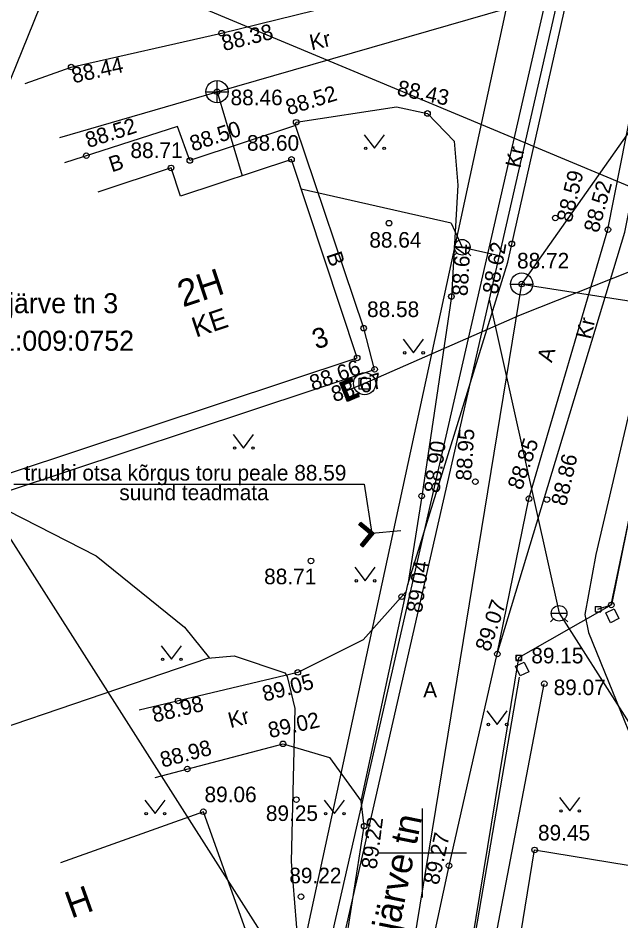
# Model space of a CAD drawing. Extents: x 648748 to 649126, y 6457789 to 6458252.
# Drawn here: x 648931.84 to 648958.94, y 6457996.94 to 6458037.5 of the extents above; entities that cross this region are included whole.
import ezdxf

# ---------------------------------------------------------------- set-up
doc = ezdxf.new("R2010")
doc.units = 0
for name, color, linetype in [('AED', 7, 'Continuous'), ('DKAEV', 7, 'Continuous'), ('HALJASTUS', 7, 'Continuous'), ('HOONE', 7, 'Continuous'), ('HOONEDET', 7, 'Continuous'), ('KKAEV', 7, 'Continuous'), ('KORGUS-EH2000', 7, 'Continuous'), ('KTRASS', 7, 'Continuous'), ('MPOHULIIN', 7, 'Continuous'), ('PIIR', 7, 'Continuous'), ('SIOHULIIN', 7, 'Continuous'), ('SITRASS', 7, 'Continuous'), ('SKTRASS', 7, 'Continuous'), ('TEE', 7, 'Continuous'), ('TRUUP', 7, 'Continuous'), ('VKAEV', 7, 'Continuous'), ('VORK', 7, 'Continuous'), ('VTRASS', 7, 'Continuous')]:
    doc.layers.add(name, color=color, linetype=linetype)

msp = doc.modelspace()

# ---------------------------------------------------------------- linework, layer by layer
at = {"layer": 'AED'}
for p, q in [((648957.78, 6458011.07), (648957.78, 6458010.82)), ((648957.78, 6458011.07), (648958.03, 6458011.07)), ((648957.78, 6458010.82), (648958.03, 6458010.82)), ((648958.03, 6458011.07), (648958.03, 6458010.82)), ((648954.219, 6458008.884), (648954.219, 6458008.634)), ((648954.219, 6458008.884), (648954.469, 6458008.884)), ((648954.469, 6458008.884), (648954.469, 6458008.634)), ((648954.219, 6458008.634), (648954.469, 6458008.634))]:
    msp.add_line(p, q, dxfattribs=at)
for points in [[(648957.905, 6458010.945), (648958.505, 6458011.137), (648959.247, 6458014.712), (648961.658, 6458026.499), (648962.069, 6458028.393), (648963.906, 6458037.666), (648968.07, 6458039.149)], [(648958.257, 6458010.775), (648958.64, 6458010.955), (648958.846, 6458010.521), (648958.463, 6458010.34), (648958.257, 6458010.775)], [(648954.203, 6458008.383), (648954.586, 6458008.564), (648954.792, 6458008.129), (648954.409, 6458007.949), (648954.203, 6458008.383)], [(648950.831, 6457987.974), (648952.234, 6457995.418), (648954.381, 6458007.899)]]:
    msp.add_lwpolyline(points, dxfattribs=at)
at = {"layer": 'DKAEV'}
for p, q in [((648947.167, 6458020.826), (648947.167, 6458021.326)), ((648947.167, 6458021.326), (648947.667, 6458021.326)), ((648947.667, 6458021.326), (648947.667, 6458020.826)), ((648947.667, 6458020.826), (648947.167, 6458020.826))]:
    msp.add_line(p, q, dxfattribs=at)
msp.add_circle((648947.417, 6458021.076), 0.5, dxfattribs=at)
at = {"layer": 'HALJASTUS'}
for p, q in [((648947.404, 6458032.255), (648947.868, 6458031.649)), ((648947.868, 6458031.649), (648948.313, 6458032.255)), ((648949.158, 6458023.067), (648949.621, 6458022.461)), ((648949.621, 6458022.461), (648950.067, 6458023.067)), ((648941.513, 6458018.789), (648941.976, 6458018.182)), ((648941.976, 6458018.182), (648942.422, 6458018.789)), ((648946.983, 6458012.827), (648947.447, 6458012.22)), ((648947.447, 6458012.22), (648947.892, 6458012.827)), ((648938.279, 6458009.303), (648938.742, 6458008.696)), ((648938.742, 6458008.696), (648939.188, 6458009.303)), ((648952.916, 6458006.373), (648953.38, 6458005.766)), ((648953.38, 6458005.766), (648953.825, 6458006.373)), ((648937.539, 6458002.37), (648938.002, 6458001.764)), ((648938.002, 6458001.764), (648938.448, 6458002.37)), ((648945.605, 6458002.37), (648946.068, 6458001.764)), ((648946.068, 6458001.764), (648946.514, 6458002.37)), ((648956.181, 6458002.49), (648956.645, 6458001.883)), ((648956.645, 6458001.883), (648957.09, 6458002.49))]:
    msp.add_line(p, q, dxfattribs=at)
msp.add_lwpolyline([(648952.124, 6457988.956), (648953.251, 6457995.928), (648955.494, 6458007.598)], dxfattribs=at)
for centre in [(648947.467, 6458031.649), (648948.296, 6458031.649), (648949.22, 6458022.461), (648950.049, 6458022.461), (648941.575, 6458018.182), (648942.404, 6458018.182), (648947.046, 6458012.22), (648947.875, 6458012.22), (648938.341, 6458008.696), (648939.17, 6458008.696), (648952.979, 6458005.766), (648953.808, 6458005.766), (648937.601, 6458001.764), (648938.43, 6458001.764), (648945.667, 6458001.764), (648946.496, 6458001.764), (648956.244, 6458001.883), (648957.073, 6458001.883)]:
    msp.add_circle(centre, 0.055, dxfattribs=at)
at = {"layer": 'HOONE'}
for points in [[(648928.367, 6458016.043), (648947.082, 6458022.232), (648944.133, 6458031.148), (648939.141, 6458029.497), (648938.721, 6458030.766), (648935.436, 6458029.68)], [(648928.544, 6457989.915), (648930.412, 6457990.585), (648929.933, 6457991.921), (648942.161, 6457996.306), (648940.174, 6458001.849), (648933.757, 6457999.547)], [(648955.058, 6458000.133), (648960.085, 6457999.314), (648958.123, 6457987.27), (648953.096, 6457988.089), (648955.058, 6458000.133)]]:
    msp.add_lwpolyline(points, dxfattribs=at)
at = {"layer": 'HOONEDET'}
msp.add_lwpolyline([(648928.604, 6458015.329), (648947.87, 6458021.718), (648947.377, 6458023.566), (648944.308, 6458032.668), (648939.566, 6458031.1), (648939.016, 6458032.625), (648933.927, 6458031.001)], dxfattribs=at)
at = {"layer": 'KKAEV'}
for p, q in [((648940.789, 6458033.688), (648940.789, 6458034.688)), ((648940.289, 6458034.188), (648941.289, 6458034.188))]:
    msp.add_line(p, q, dxfattribs=at)
msp.add_circle((648940.789, 6458034.188), 0.5, dxfattribs=at)
at = {"layer": 'KORGUS-EH2000'}
for centre in [(648940.99, 6458036.816), (648934.231, 6458035.294), (648940.789, 6458034.188), (648950.246, 6458033.212), (648944.345, 6458032.817), (648934.911, 6458031.315), (648939.566, 6458031.1), (648944.133, 6458031.148), (648938.721, 6458030.766), (648955.988, 6458028.516), (648948.514, 6458028.286), (648958.354, 6458027.992), (648954.032, 6458027.355), (648954.479, 6458025.55), (648951.32, 6458024.991), (648947.377, 6458023.566), (648947.082, 6458022.232), (648947.87, 6458021.718), (648952.398, 6458016.673), (648949.986, 6458016.028), (648954.806, 6458015.908), (648955.61, 6458015.868), (648945.007, 6458013.112), (648949.087, 6458011.505), (648958.505, 6458011.137), (648953.382, 6458008.934), (648954.344, 6458008.759), (648944.419, 6458008.105), (648955.494, 6458007.598), (648939.039, 6458006.826), (648943.752, 6458004.898), (648939.455, 6458003.768), (648944.351, 6458002.393), (648940.174, 6458001.849), (648947.397, 6458001.199), (648955.058, 6458000.133), (648951.214, 6457999.425), (648944.563, 6457998.032)]:
    msp.add_circle(centre, 0.125, dxfattribs=at)
at = {"layer": 'KTRASS'}
for p, q in [((648940.789, 6458034.188), (648955.59, 6458038.453)), ((648955.59, 6458038.453), (648945.475, 6457994.285)), ((648933.724, 6458032.135), (648940.789, 6458034.188)), ((648940.789, 6458034.188), (648941.911, 6458030.413))]:
    msp.add_line(p, q, dxfattribs=at)
at = {"layer": 'MPOHULIIN'}
for points in [[(648933.863, 6458040.57), (648928.888, 6458028.309)], [(648951.387, 6457937.05), (648959.585, 6457983.976), (648966.776, 6458026.817), (648933.863, 6458040.57)]]:
    msp.add_lwpolyline(points, dxfattribs=at)
at = {"layer": 'PIIR'}
for p, q in [((648941.03, 6457978.89), (648955.2, 6458044.42)), ((648963.88, 6458037.67), (648958.51, 6458011.14)), ((648958.51, 6458011.14), (648954.34, 6458008.76)), ((648954.34, 6458008.76), (648949.37, 6457978.67))]:
    msp.add_line(p, q, dxfattribs=at)
at = {"layer": 'SIOHULIIN'}
msp.add_line((648950.018, 6457985.085), (648929.935, 6458016.562), dxfattribs=at)
at = {"layer": 'SITRASS'}
for points in [[(648966.11, 6458089.841), (648964.318, 6458080.667), (648962.235, 6458070.833), (648961.742, 6458067.306), (648960.68, 6458062.734), (648960.081, 6458059.549), (648958.829, 6458053.903), (648959.436, 6458052.488), (648962.102, 6458051.731), (648964.818, 6458051.004), (648965.35, 6458050.106), (648964.898, 6458046.706), (648961.929, 6458032.449), (648960.742, 6458025.938), (648957.809, 6458013.402), (648957.321, 6458010.707), (648957.473, 6458009.892), (648960.884, 6458001.538), (648961.927, 6457999.033), (648963.394, 6457991.382), (648965.2, 6457986.983), (648965.946, 6457985.459)], [(648929.395, 6458016.383), (648935.351, 6458013.347), (648939.325, 6458010.138), (648940.451, 6458008.746)], [(648924.967, 6458003.499), (648940.379, 6458008.739), (648941.56, 6458008.853), (648943.833, 6458008.084), (648943.941, 6458007.928), (648944.279, 6458006.478), (648944.124, 6457999.614), (648944.415, 6457995.906), (648943.985, 6457992.031), (648941.907, 6457992.28), (648941.694, 6457991.996)]]:
    msp.add_lwpolyline(points, dxfattribs=at)
at = {"layer": 'SKTRASS'}
for p, q in [((648946.306, 6458021.116), (648946.84, 6458021.33)), ((648946.621, 6458021.08), (648946.703, 6458021.275)), ((648946.653, 6458021.093), (648946.736, 6458021.288)), ((648946.686, 6458021.107), (648946.768, 6458021.302)), ((648946.718, 6458021.12), (648946.801, 6458021.315)), ((648946.751, 6458021.133), (648946.834, 6458021.328)), ((648946.784, 6458021.146), (648946.85, 6458021.303)), ((648946.817, 6458021.159), (648946.864, 6458021.27)), ((648946.896, 6458021.191), (648946.84, 6458021.33)), ((648946.642, 6458020.281), (648946.306, 6458021.116)), ((648946.308, 6458021.111), (648946.31, 6458021.117)), ((648946.321, 6458021.078), (648946.343, 6458021.13)), ((648946.334, 6458021.046), (648946.376, 6458021.144)), ((648946.348, 6458021.013), (648946.408, 6458021.157)), ((648946.361, 6458020.98), (648946.441, 6458021.17)), ((648946.374, 6458020.947), (648946.474, 6458021.183)), ((648946.387, 6458020.914), (648946.507, 6458021.196)), ((648946.401, 6458020.881), (648946.539, 6458021.209)), ((648946.404, 6458021.074), (648946.868, 6458021.261)), ((648946.684, 6458020.378), (648946.404, 6458021.074)), ((648946.414, 6458020.848), (648946.572, 6458021.223)), ((648946.427, 6458020.815), (648946.51, 6458021.012)), ((648946.44, 6458020.783), (648946.523, 6458020.979)), ((648946.454, 6458020.75), (648946.536, 6458020.946)), ((648946.467, 6458020.717), (648946.55, 6458020.913)), ((648946.48, 6458020.684), (648946.563, 6458020.88)), ((648946.501, 6458021.032), (648946.896, 6458021.191)), ((648946.725, 6458020.476), (648946.501, 6458021.032)), ((648946.522, 6458021.041), (648946.605, 6458021.236)), ((648946.555, 6458021.054), (648946.637, 6458021.249)), ((648946.588, 6458021.067), (648946.67, 6458021.262)), ((648946.849, 6458021.172), (648946.877, 6458021.238)), ((648946.882, 6458021.186), (648946.89, 6458021.205)), ((648946.493, 6458020.651), (648946.576, 6458020.847)), ((648946.506, 6458020.618), (648946.589, 6458020.814)), ((648946.52, 6458020.585), (648946.602, 6458020.781)), ((648946.533, 6458020.552), (648946.616, 6458020.749)), ((648946.546, 6458020.52), (648946.629, 6458020.716)), ((648946.559, 6458020.487), (648946.642, 6458020.683)), ((648946.573, 6458020.454), (648946.655, 6458020.65)), ((648946.586, 6458020.421), (648946.669, 6458020.617)), ((648946.599, 6458020.388), (648946.682, 6458020.584)), ((648946.612, 6458020.355), (648946.695, 6458020.551)), ((648946.626, 6458020.322), (648946.708, 6458020.518)), ((648946.639, 6458020.289), (648946.722, 6458020.486)), ((648947.176, 6458020.495), (648946.642, 6458020.281)), ((648946.666, 6458020.29), (648946.749, 6458020.485)), ((648947.148, 6458020.565), (648946.684, 6458020.378)), ((648946.699, 6458020.303), (648946.782, 6458020.498)), ((648947.12, 6458020.635), (648946.725, 6458020.476)), ((648946.732, 6458020.317), (648946.814, 6458020.511)), ((648946.764, 6458020.33), (648946.847, 6458020.525)), ((648946.797, 6458020.343), (648946.879, 6458020.538)), ((648946.83, 6458020.356), (648946.912, 6458020.551)), ((648946.863, 6458020.369), (648946.945, 6458020.564)), ((648946.895, 6458020.382), (648946.978, 6458020.577)), ((648946.928, 6458020.396), (648947.01, 6458020.59)), ((648946.961, 6458020.409), (648947.043, 6458020.604)), ((648946.993, 6458020.422), (648947.076, 6458020.617)), ((648947.026, 6458020.435), (648947.109, 6458020.63)), ((648947.059, 6458020.448), (648947.129, 6458020.613)), ((648947.092, 6458020.462), (648947.142, 6458020.58)), ((648947.176, 6458020.495), (648947.12, 6458020.635)), ((648947.124, 6458020.475), (648947.155, 6458020.547)), ((648947.157, 6458020.488), (648947.168, 6458020.514))]:
    msp.add_line(p, q, dxfattribs=at)
for points in [[(648960.26, 6458026.478), (648954.414, 6458024.157), (648947.417, 6458021.076)], [(648947.417, 6458021.076), (648946.544, 6458020.726)]]:
    msp.add_lwpolyline(points, dxfattribs=at)
at = {"layer": 'TEE'}
for points in [[(648944.322, 6457942.691), (648944.43, 6457950.272), (648943.62, 6457959.958), (648943.695, 6457961.993), (648942.732, 6457979.09), (648943.931, 6457987.913), (648944.971, 6457991.084), (648946.572, 6457995.932), (648947.397, 6458001.199), (648947.266, 6458002.317), (648949.36, 6458012.048), (648953.85, 6458026.527), (648957.912, 6458044.595), (648958.876, 6458046.069), (648959.537, 6458047.72), (648961.311, 6458058.347), (648962.735, 6458068.115), (648964.651, 6458078.174), (648966.451, 6458083.821)], [(648949.689, 6457988.093), (648949.022, 6457989.19), (648951.214, 6457999.425), (648953.382, 6458008.934), (648954.806, 6458015.908), (648958.354, 6458027.992), (648959.727, 6458034.967), (648961.147, 6458039.663), (648962.725, 6458047.115), (648963.962, 6458052.11), (648965.802, 6458054.388), (648967.969, 6458055.624), (648969.67, 6458055.74), (648971.091, 6458054.761), (648978.388, 6458045.705), (649000.128, 6458020.255), (649018.273, 6457999), (649024.176, 6457993.684), (649043.03, 6457975.251)], [(648932.159, 6458034.561), (648934.231, 6458035.294), (648940.99, 6458036.816), (648948.491, 6458038.681), (648954.051, 6458040.763), (648956.882, 6458043.195), (648957.912, 6458044.595)], [(648953.382, 6458008.934), (648959.109, 6458027.881), (648961.591, 6458040.215)], [(648944.308, 6458032.668), (648944.345, 6458032.817), (648948.853, 6458033.502), (648950.246, 6458033.212), (648951.447, 6458031.971), (648951.613, 6458029.985), (648951.32, 6458024.991), (648949.986, 6458016.028), (648949.36, 6458012.048)], [(648949.293, 6458011.734), (648947.353, 6458009.575), (648944.419, 6458008.105), (648937.294, 6458006.411)], [(648938.012, 6458003.389), (648943.752, 6458004.898), (648945.845, 6458004.277), (648947.266, 6458002.317)]]:
    msp.add_lwpolyline(points, dxfattribs=at)
at = {"layer": 'TRUUP'}
for p, q in [((648947.155, 6458014.736), (648947.246, 6458014.846)), ((648947.159, 6458014.733), (648947.306, 6458014.797)), ((648947.183, 6458014.771), (648947.284, 6458014.815)), ((648947.744, 6458014.339), (648947.201, 6458014.791)), ((648947.219, 6458014.814), (648947.263, 6458014.833)), ((648947.844, 6458014.349), (648947.246, 6458014.846)), ((648947.644, 6458014.33), (648947.155, 6458014.736)), ((648947.181, 6458014.715), (648947.327, 6458014.779)), ((648947.202, 6458014.697), (648947.349, 6458014.761)), ((648947.224, 6458014.68), (648947.37, 6458014.743)), ((648947.246, 6458014.661), (648947.392, 6458014.725)), ((648947.267, 6458014.644), (648947.413, 6458014.707)), ((648947.289, 6458014.626), (648947.435, 6458014.689)), ((648947.31, 6458014.608), (648947.456, 6458014.671)), ((648947.332, 6458014.59), (648947.478, 6458014.654)), ((648947.353, 6458014.572), (648947.499, 6458014.636)), ((648947.375, 6458014.554), (648947.521, 6458014.618)), ((648947.396, 6458014.536), (648947.542, 6458014.6)), ((648947.418, 6458014.518), (648947.564, 6458014.582)), ((648947.439, 6458014.501), (648947.586, 6458014.564)), ((648947.461, 6458014.482), (648947.607, 6458014.546)), ((648947.482, 6458014.465), (648947.629, 6458014.528)), ((648947.504, 6458014.447), (648947.65, 6458014.51)), ((648947.525, 6458014.429), (648947.672, 6458014.492)), ((648947.547, 6458014.411), (648947.693, 6458014.475)), ((648947.568, 6458014.393), (648947.715, 6458014.457)), ((648947.59, 6458014.375), (648947.736, 6458014.439)), ((648947.612, 6458014.357), (648947.757, 6458014.421)), ((648947.627, 6458014.31), (648947.801, 6458014.385)), ((648947.633, 6458014.339), (648947.779, 6458014.403)), ((648949.04, 6458014.459), (648947.744, 6458014.339)), ((648947.237, 6458013.841), (648947.644, 6458014.33)), ((648947.272, 6458013.882), (648947.562, 6458014.009)), ((648947.292, 6458013.796), (648947.744, 6458014.339)), ((648947.308, 6458013.925), (648947.598, 6458014.051)), ((648947.343, 6458013.968), (648947.633, 6458014.094)), ((648947.347, 6458013.75), (648947.844, 6458014.349)), ((648947.379, 6458014.01), (648947.669, 6458014.137)), ((648947.414, 6458014.053), (648947.704, 6458014.18)), ((648947.45, 6458014.096), (648947.74, 6458014.222)), ((648947.485, 6458014.139), (648947.775, 6458014.265)), ((648947.52, 6458014.181), (648947.811, 6458014.308)), ((648947.556, 6458014.224), (648947.844, 6458014.35)), ((648947.591, 6458014.267), (648947.822, 6458014.367)), ((648947.237, 6458013.841), (648947.347, 6458013.75)), ((648947.239, 6458013.84), (648947.526, 6458013.966)), ((648947.26, 6458013.823), (648947.491, 6458013.923)), ((648947.282, 6458013.805), (648947.455, 6458013.88)), ((648947.303, 6458013.787), (648947.42, 6458013.838)), ((648947.324, 6458013.769), (648947.384, 6458013.795))]:
    msp.add_line(p, q, dxfattribs=at)
msp.add_lwpolyline([(648931.655, 6458016.554), (648947.401, 6458016.554), (648947.744, 6458014.339)], dxfattribs=at)
at = {"layer": 'VKAEV'}
for p, q in [((648951.56, 6458026.956), (648951.42, 6458026.816)), ((648951.457, 6458027.203), (648952.157, 6458027.203)), ((648952.055, 6458026.956), (648952.194, 6458026.816)), ((648953.979, 6458025.55), (648954.979, 6458025.55)), ((648955.807, 6458010.76), (648956.507, 6458010.76)), ((648955.91, 6458010.513), (648955.77, 6458010.373)), ((648956.405, 6458010.513), (648956.544, 6458010.373))]:
    msp.add_line(p, q, dxfattribs=at)
for centre, radius in [((648951.807, 6458027.203), 0.35), ((648954.479, 6458025.55), 0.5), ((648956.157, 6458010.76), 0.35)]:
    msp.add_circle(centre, radius, dxfattribs=at)
at = {"layer": 'VORK'}
for p, q in [((648950, 6458002), (648950, 6457998)), ((648948, 6458000), (648952, 6458000))]:
    msp.add_line(p, q, dxfattribs=at)
at = {"layer": 'VTRASS'}
for p, q in [((648951.309, 6458028.291), (648944.573, 6458029.817)), ((648942.899, 6457954.736), (648954.479, 6458025.55)), ((648954.479, 6458025.55), (648965.614, 6458023.815))]:
    msp.add_line(p, q, dxfattribs=at)
for points in [[(648954.479, 6458025.55), (648956.102, 6458027.829), (648982.087, 6458064.694)], [(648962.127, 6458064.182), (648961.879, 6458062.803), (648959.226, 6458048.095), (648956.066, 6458038.246), (648953.46, 6458026.826), (648953.015, 6458024.876), (648946.034, 6457994.282), (648943.505, 6457961.801)], [(648951.309, 6458028.291), (648951.807, 6458027.203), (648953.46, 6458026.826)], [(648953.015, 6458024.876), (648956.157, 6458010.76), (648969.796, 6457989.383)]]:
    msp.add_lwpolyline(points, dxfattribs=at)

# ---------------------------------------------------------------- texts
at = {"layer": 'HOONE'}
for s, height, rotation, p in [('2H', 1.2, 18.2991, (648939.251, 6458024.497)), ('KE', 0.9, 18.2991, (648939.835, 6458023.14)), ('3', 0.9, 18.2991, (648945.239, 6458022.605)), ('H', 1.2, 19.7291, (648934.232, 6457997.043))]:
    msp.add_text(s, height=height, rotation=rotation, dxfattribs=at).set_placement(p)
at = {"layer": 'HOONEDET'}
for rotation, p in [(18.2991, (648936.06, 6458030.564)), (288.2991, (648945.692, 6458026.87))]:
    msp.add_text('B', height=0.7, rotation=rotation, dxfattribs=at).set_placement(p)
at = {"layer": 'KORGUS-EH2000'}
for s, rotation, p in [('88.38', 13.9609, (648941.092, 6458036.01)), ('88.44', 12.6941, (648934.338, 6458034.561)), ('88.43', 348.232, (648948.836, 6458034.037)), ('88.52', 17.2747, (648944.003, 6458033.125)), ('88.52', 17.7092, (648935, 6458031.655)), ('88.50', 18.2949, (648939.699, 6458031.497)), ('88.59', 76.4191, (648956.714, 6458028.276)), ('88.52', 74.6088, (648957.924, 6458027.815)), ('88.62', 80.1099, (648953.394, 6458025.061)), ('88.64', 86.6434, (648952.043, 6458024.995)), ('88.66', 19.3673, (648945.091, 6458020.743)), ('88.67', 16.7239, (648946.042, 6458020.245)), ('88.95', 86.3283, (648952.208, 6458016.697)), ('88.90', 82.9477, (648950.78, 6458016.137)), ('88.85', 70.803, (648954.479, 6458016.259)), ('88.86', 77.0674, (648956.47, 6458015.544)), ('89.04', 81.9174, (648949.989, 6458010.748)), ('89.07', 71.0033, (648953.028, 6458008.999)), ('89.05', 15.0464, (648942.924, 6458006.785)), ('88.98', 13.3728, (648937.958, 6458005.846)), ('89.02', 12.5288, (648943.165, 6458005.153)), ('88.98', 14.7323, (648938.333, 6458003.823)), ('89.22', 82.7183, (648947.956, 6457999.243)), ('89.27', 77.3609, (648950.74, 6457998.529))]:
    msp.add_text(s, height=0.7, rotation=rotation, dxfattribs=at).set_placement(p)
for s, p in [('88.46', (648941.394, 6458033.581)), ('88.60', (648942.132, 6458031.539)), ('88.71', (648936.895, 6458031.21)), ('88.64', (648947.63, 6458027.184)), ('88.72', (648954.27, 6458026.251)), ('88.58', (648947.528, 6458024.067)), ('88.71', (648942.903, 6458012.065)), ('89.15', (648954.909, 6458008.512)), ('89.07', (648955.912, 6458007.085)), ('89.06', (648940.224, 6458002.275)), ('89.25', (648942.981, 6458001.433)), ('89.45', (648955.21, 6458000.555)), ('89.22', (648944.034, 6457998.634))]:
    msp.add_text(s, height=0.7, dxfattribs=at).set_placement(p)
at = {"layer": 'PIIR'}
for s, p in [('Vanajärve tn 3', (648928.583, 6458024.24)), ('52801:009:0752', (648928.355, 6458022.554))]:
    msp.add_text(s, height=0.9, dxfattribs=at).set_placement(p)
at = {"layer": 'TEE'}
for s, height, rotation, p in [('Kr', 0.7, 12.6941, (648945.032, 6458036.049)), ('Kr', 0.7, 77.4029, (648954.416, 6458030.724)), ('Kr', 0.7, 77.4029, (648957.584, 6458023.037)), ('A', 0.7, 73.638, (648955.828, 6458021.995)), ('Kr', 0.7, 14.7323, (648941.389, 6458005.601)), ('Vanajärve tn', 1.2, 78.3735, (648948.19, 6457992.775))]:
    msp.add_text(s, height=height, rotation=rotation, dxfattribs=at).set_placement(p)
msp.add_text('A', height=0.7, dxfattribs=at).set_placement((648950.052, 6458006.981))
at = {"layer": 'TRUUP'}
for s, p in [('truubi otsa kõrgus toru peale 88.59', (648932.133, 6458016.722)), ('suund teadmata', (648936.395, 6458015.838))]:
    msp.add_text(s, height=0.7, dxfattribs=at).set_placement(p)

doc.saveas('drawing.dxf')
